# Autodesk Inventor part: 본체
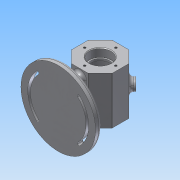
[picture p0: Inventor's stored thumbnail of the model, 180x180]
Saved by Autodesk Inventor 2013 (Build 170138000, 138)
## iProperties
Created: 2017-06
Part Number: 본체
Material: 알루미늄 6061
Document SubType Name: Modeling
Designer: Administrator
Density: 2.71 g/cm^3
Mass: 559.93 g
Surface Area: 562.162 cm^2
Volume: 206.616 cm^3
Author: Administrator
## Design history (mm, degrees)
sketch "스케치1" dims "d0" = 60
  geometry: L1 (-12.426, -30)-(-30, -12.426); L2 (-30, -12.426)-(-30, 12.426); L3 (-30, 12.426)-(-12.426, 30); L4 (-12.426, 30)-(12.426, 30); L5 (12.426, 30)-(30, 12.426); L6 (30, 12.426)-(30, -12.426); L7 (30, -12.426)-(12.426, -30); L8 (12.426, -30)-(-12.426, -30); 4 further points
  constraints: 16 end point, 2 coincident, 1 midpoint, 1 vertical alignment, 19 other
extrude "돌출1" new body sketch "스케치1" stored distance "d1" = 70; taper "d2" = 0 deg
sketch "스케치2"
  geometry: L1 (0, 35)-(0, -35); L2 (0, -35)-(16, -35); L3 (16, -35)-(16, -23); L4 (16, -23)-(14, -23); L5 (14, -23)-(14, -20); L6 (14, -20)-(25, -20); L7 (25, -20)-(25, 20); L8 (25, 20)-(14, 20); L9 (14, 20)-(14, 23); L10 (14, 23)-(16, 23); L11 (16, 23)-(16, 35); L12 (16, 35)-(0, 35); 2 further points
  constraints: 24 end point, 6 parallel, 5 perpendicular, 4 equal length, 1 coincident, 1 midpoint, 1 vertical
  dimensions: "d3" = 50 diameter of L7 L1; "d5" = 28 diameter of L5 L1; "d6" = 32 diameter of L3 L1; "d8" = 3 distance of L4.end L5.end; "d9" = 12 distance of L2.end L3.end; "d10" = 40 distance of L6.end L7.end
revolve "회전1" sketch "스케치2" stored, may be unused: angle "d11" = 90 deg
node "작업 평면1"
sketch "스케치3"
  geometry: C1 r 55 at (0, 0); 1 further point
  constraints: 1 centre point, 1 coincident
  dimensions: "d13" = 110 diameter of C1
extrude "돌출2" join sketch "스케치3" distance "d14" = 10; taper "d15" = 0 deg
sketch "스케치4"
  geometry: L1 (0, 0)-(-30.406, -30.406); L2 (0, 0)-(43, 0); L3 (0, 0)-(-30.406, 30.406); C1 r 55 at (0, 0) reference; A1 r 48 centre (0, 0) between (-33.941, 33.941) and (-33.941, -33.941); A2 r 38 centre (0, 0) between (-26.87, 26.87) and (-26.87, -26.87); A3 r 5 centre (-30.406, -30.406) between (-33.941, -33.941) and (-26.87, -26.87); A4 r 5 centre (-30.406, 30.406) between (-26.87, 26.87) and (-33.941, 33.941)
  constraints: 8 point on circle, 6 end point, 5 coincident, 4 centre point, 1 equal length, 1 horizontal, 1 perpendicular
  dimensions: "d16" = 96 diameter of A1; "d17" = 76 diameter of A2; "d18" = 43 distance of L1.start L1.end; "d19" = 135 deg angle of L1 L2; "d20" = 43 distance of L1.start L3.end; "d21" = 10 diameter of A3; "d22" = 10 diameter of A4
extrude "돌출3" cut sketch "스케치4" distance "d23" = 3; taper "d24" = 0 deg
sketch "스케치5"
  geometry: A1 r 38 centre (0, 0) between (-26.87, 26.87) and (-26.87, -26.87) reference; A2 r 5 centre (-30.406, 30.406) between (-26.87, 26.87) and (-33.941, 33.941) reference; A3 r 48 centre (0, 0) between (-33.941, 33.941) and (-33.941, -33.941) reference; A4 r 5 centre (-30.406, -30.406) between (-33.941, -33.941) and (-26.87, -26.87) reference; A5 r 2 centre (-30.406, 30.406) between (-28.991, 28.991) and (-31.82, 31.82); A6 r 41 centre (0, 0) between (-28.991, 28.991) and (-28.991, -28.991); A7 r 2 centre (-30.406, -30.406) between (-31.82, -31.82) and (-28.991, -28.991); A8 r 45 centre (0, 0) between (-31.82, 31.82) and (-31.82, -31.82)
  constraints: 8 point on circle, 4 centre point, 3 other
  dimensions: "d25" = 2 radius of A5
extrude "돌출4" cut sketch "스케치5" stored distance "d27" = 3; taper "d28" = 0 deg
sketch "스케치6"
  geometry: L1 (-5, -24)-(5, -24); L2 (5, -24)-(5, 24); L3 (5, 24)-(-5, 24); L4 (-5, 24)-(-5, -24); L5 (-5, -24)-(5, 24); L6 (5, -24)-(-5, 24); C1 r 55 at (0, 0) reference; C2 r 5 at (0, 24); C3 r 5 at (0, -24)
  constraints: 12 end point, 4 midpoint, 2 centre point, 2 parallel, 1 horizontal, 1 perpendicular
  dimensions: "d29" = 10 distance of L3.end L2.end; "d30" = 48 distance of L2.end L1.end; "d31" = 10 diameter of C2; "d32" = 10 diameter of C3
extrude "돌출5" join sketch "스케치6" stored distance "d33" = 3; taper "d34" = 0 deg
sketch "스케치7"
  geometry: L1 (0, 0)-(26.163, 26.163); L2 (0, 0)-(37, 0)
  constraints: 4 end point, 1 equal length, 1 horizontal
  dimensions: "d35" = 37 distance of L1.start L1.end; "d36" = 45 deg angle of L2 L1
node "작업 평면2"
sketch "스케치8"
  geometry: C1 r 8 at (0, 0); 1 further point
  constraints: 1 centre point, 1 coincident
  dimensions: "d37" = 16 diameter of C1
extrude "돌출6" join sketch "스케치8" stored distance "d38" = 3; taper "d39" = 0 deg
hole "구멍1" diameter "d42" = 8; stored, may be unused: countersink angle "d46" = 90 deg, drill point angle "d48" = 118 deg; dims "d40" = 10, "d41" = 10, "d43" = 6, "d44" = 4, "d45" = 2, "d47" = 8
sketch "스케치9"
  geometry: C1 r 16 at (0, 0) reference; 1 further point
  constraints: 1 vertical alignment
  dimensions: "d49" = 23 distance of C1.centre point (0, 23)
hole "구멍2" sketch "스케치9" at (0, 23) diameter "d50" = 3.242; stored, may be unused: countersink angle "d54" = 90 deg, drill point angle "d56" = 118 deg; dims "d51" = 8, "d52" = 4, "d53" = 2, "d55" = 10
fillet "모깎기1" dims "d60" = 1, "d61" = 5, "d62" = 5
fillet "모깎기2" dims "d63" = 3, "d64" = 0.3
chamfer "모따기1" distance "d65" = 1; stored, may be unused: second distance "d66" = 2, angle "d67" = 45 deg
sketch "스케치10"
  geometry: L1 (24.024, 0)-(0, 0) reference; 2 further points
  constraints: 1 coincident, 1 other
  dimensions: "d68" = 35 distance from line of L1 point (12.012, 35)
feature "엠보싱1" sketch "스케치10" dims "d3" = 50, "d5" = 28, "d6" = 32, "d8" = 3, "d9" = 12, "d10" = 40, "d69" = 0.5, "d70" = 0
node "솔리드1"
mirror "대칭1"
pattern_circular "원형 패턴1" dims angle "d58" = 360 deg
mirror "대칭2"
other parameters: "d12" = -62
